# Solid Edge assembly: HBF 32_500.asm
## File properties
Title: Zylinder
Author: ahadarics
Template: iso assembly.asm
Last saved by: ahadarics
Revision: 30
Application: Solid Edge
Username: ahadarics
Dokumentum tartalom típus: 1
Document Number: HBF 32/500
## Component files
Profilrohr 32_500.par
Mutter.par
Kolbenstange_1_32_500.par
Kit.par
Kolbenstange_2_32_500.par
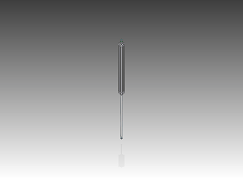
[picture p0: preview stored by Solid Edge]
